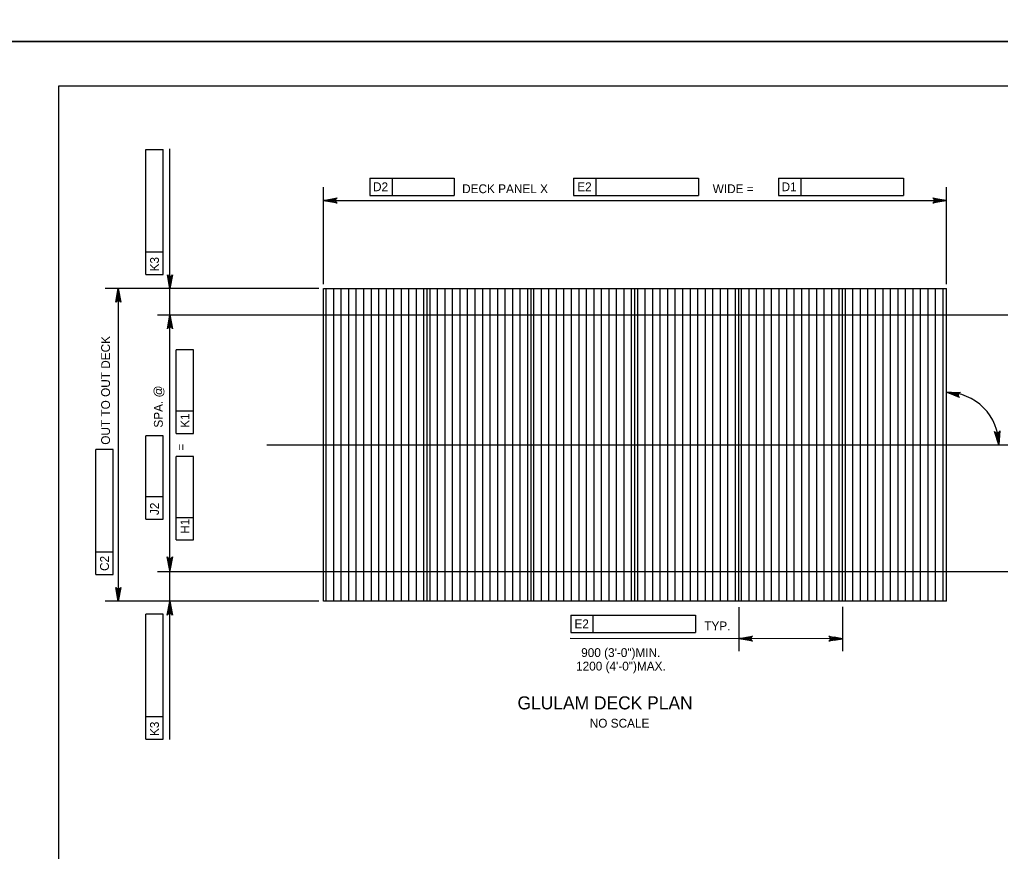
# Model space of a CAD drawing. Extents: x 638263 to 640360, y 293683 to 298655.
# Drawn here: x 639303.1 to 639636.8, y 295784 to 296067 of the extents above; entities that cross this region are included whole.
import ezdxf

# ---------------------------------------------------------------- set-up
doc = ezdxf.new("R2010")
doc.units = 0
for name, color, linetype in [('2', 7, 'Continuous'), ('4', 7, 'Continuous'), ('5', 7, 'Continuous'), ('PLT-BNDY', 7, 'Continuous')]:
    doc.layers.add(name, color=color, linetype=linetype)

msp = doc.modelspace()

# ---------------------------------------------------------------- linework, layer by layer
at = {"layer": '2'}
for p, q in [((639316.46, 295480.46), (639316.46, 296044.46)), ((639316.46, 296044.46), (640102.46, 296044.46)), ((639406.47, 295975.43), (639618.44, 295975.43)), ((639406.47, 295869.13), (639406.47, 295975.43)), ((639441.8, 295869.13), (639441.8, 295975.43)), ((639477.13, 295869.13), (639477.13, 295975.43)), ((639512.46, 295869.13), (639512.46, 295975.43)), ((639547.78, 295869.13), (639547.78, 295975.43)), ((639583.11, 295869.13), (639583.11, 295975.43)), ((639618.44, 295869.13), (639618.44, 295975.43)), ((639618.44, 295869.13), (639406.47, 295869.13))]:
    msp.add_line(p, q, dxfattribs=at)
at = {"layer": '4'}
for p, q in [((639346.04, 295980.26), (639346.04, 296022.78)), ((639346.04, 296022.78), (639351.95, 296022.78)), ((639351.95, 295980.26), (639351.95, 296022.78)), ((639354.25, 295822.05), (639354.25, 296023.02)), ((639422.27, 296013.03), (639450.94, 296013.03)), ((639422.27, 296013.03), (639422.27, 296007.12)), ((639429.83, 296013.03), (639429.83, 296007.12)), ((639450.94, 296013.03), (639450.94, 296007.12)), ((639491.54, 296013.03), (639534.06, 296013.03)), ((639491.54, 296013.03), (639491.54, 296007.12)), ((639499.1, 296013.03), (639499.1, 296007.12)), ((639534.06, 296013.03), (639534.06, 296007.12)), ((639561.33, 296013.03), (639603.85, 296013.03)), ((639561.33, 296013.03), (639561.33, 296007.12)), ((639568.89, 296013.03), (639568.89, 296007.12)), ((639603.85, 296013.03), (639603.85, 296007.12)), ((639406.47, 295976.99), (639406.47, 296009.91)), ((639422.27, 296007.12), (639450.94, 296007.12)), ((639491.54, 296007.12), (639534.06, 296007.12)), ((639561.33, 296007.12), (639603.85, 296007.12)), ((639618.44, 295976.99), (639618.44, 296009.91)), ((639406.47, 296005.41), (639618.44, 296005.41)), ((639351.95, 295987.82), (639346.04, 295987.82)), ((639346.04, 295980.26), (639351.95, 295980.26)), ((639404.91, 295975.43), (639332.16, 295975.43)), ((639336.66, 295975.43), (639336.66, 295869.13)), ((639349.96, 295966.46), (639640.33, 295966.46)), ((639356.4, 295926.16), (639356.4, 295954.56)), ((639362.31, 295954.56), (639356.4, 295954.56)), ((639362.31, 295926.15), (639362.31, 295954.56)), ((639362.31, 295933.71), (639356.4, 295933.72)), ((639346.04, 295896.98), (639346.04, 295925.39)), ((639351.95, 295925.38), (639346.04, 295925.39)), ((639351.95, 295896.98), (639351.95, 295925.38)), ((639356.4, 295926.16), (639362.31, 295926.15)), ((639329.03, 295878.19), (639329.03, 295920.71)), ((639334.93, 295920.71), (639329.03, 295920.71)), ((639334.93, 295878.18), (639334.93, 295920.71)), ((639387.19, 295922.28), (639640.33, 295922.28)), ((639356.4, 295889.93), (639356.4, 295918.33)), ((639362.31, 295918.33), (639356.4, 295918.33)), ((639362.31, 295889.92), (639362.31, 295918.33)), ((639351.95, 295904.54), (639346.04, 295904.55)), ((639346.04, 295896.98), (639351.95, 295896.98)), ((639362.31, 295897.48), (639356.4, 295897.49)), ((639356.4, 295889.93), (639362.31, 295889.92)), ((639334.93, 295885.75), (639329.03, 295885.75)), ((639329.03, 295878.19), (639334.93, 295878.18)), ((639349.96, 295879.19), (639640.33, 295879.19)), ((639404.91, 295869.13), (639332.16, 295869.13)), ((639547.78, 295867.06), (639547.78, 295852.08)), ((639583.11, 295867.13), (639583.1, 295852.08)), ((639346.04, 295822.18), (639346.04, 295864.7)), ((639351.95, 295864.69), (639346.04, 295864.7)), ((639351.95, 295822.17), (639351.95, 295864.69)), ((639490.59, 295864.32), (639533.11, 295864.32)), ((639490.59, 295864.32), (639490.59, 295858.42)), ((639498.15, 295864.32), (639498.15, 295858.42)), ((639533.11, 295864.32), (639533.11, 295858.42)), ((639490.59, 295858.42), (639533.11, 295858.42)), ((639583.11, 295856.33), (639490.4, 295856.35)), ((639351.95, 295829.73), (639346.04, 295829.74)), ((639346.04, 295822.18), (639351.95, 295822.17))]:
    msp.add_line(p, q, dxfattribs=at)
for points in [[(639406.47, 296005.41), (639411.13, 296006.28), (639410.77, 296006.03), (639410.59, 296005.72), (639410.53, 296005.41), (639410.59, 296005.09), (639410.77, 296004.78), (639411.13, 296004.53), (639406.47, 296005.41), (639410.77, 296004.78), (639410.59, 296005.09), (639406.47, 296005.41), (639410.53, 296005.41), (639410.59, 296005.72), (639406.47, 296005.41), (639410.77, 296006.03)], [(639618.44, 296005.41), (639613.78, 296004.53), (639614.14, 296004.78), (639614.32, 296005.09), (639614.38, 296005.41), (639614.32, 296005.72), (639614.14, 296006.03), (639613.78, 296006.28), (639618.44, 296005.41), (639614.14, 296006.03), (639614.32, 296005.72), (639618.44, 296005.41), (639614.38, 296005.41), (639614.32, 296005.09), (639618.44, 296005.41), (639614.14, 296004.78)], [(639354.25, 295975.43), (639353.38, 295980.09), (639353.62, 295979.73), (639353.94, 295979.54), (639354.25, 295979.49), (639354.56, 295979.54), (639354.87, 295979.73), (639355.12, 295980.09), (639354.25, 295975.43), (639354.87, 295979.73), (639354.56, 295979.54), (639354.25, 295975.43), (639354.25, 295979.49), (639353.94, 295979.54), (639354.25, 295975.43), (639353.62, 295979.73)], [(639336.66, 295975.43), (639337.54, 295970.77), (639337.29, 295971.12), (639336.98, 295971.31), (639336.66, 295971.36), (639336.35, 295971.31), (639336.04, 295971.12), (639335.79, 295970.77), (639336.66, 295975.43), (639336.04, 295971.12), (639336.35, 295971.31), (639336.66, 295975.43), (639336.66, 295971.36), (639336.98, 295971.31), (639336.66, 295975.43), (639337.29, 295971.12)], [(639354.25, 295966.46), (639355.12, 295961.8), (639354.87, 295962.16), (639354.56, 295962.34), (639354.25, 295962.4), (639353.94, 295962.34), (639353.62, 295962.16), (639353.38, 295961.8), (639354.25, 295966.46), (639353.62, 295962.16), (639353.94, 295962.34), (639354.25, 295966.46), (639354.25, 295962.4), (639354.56, 295962.34), (639354.25, 295966.46), (639354.87, 295962.16)], [(639618.45, 295940.18), (639623.19, 295940.14), (639622.79, 295939.96), (639622.54, 295939.69), (639622.43, 295939.4), (639622.42, 295939.08), (639622.55, 295938.74), (639622.85, 295938.42), (639618.45, 295940.18), (639622.55, 295938.74), (639622.42, 295939.08), (639618.45, 295940.18), (639622.43, 295939.4), (639622.54, 295939.69), (639618.45, 295940.18), (639622.79, 295939.96)], [(639636.29, 295922.28), (639634.83, 295926.79), (639635.13, 295926.47), (639635.46, 295926.32), (639635.78, 295926.31), (639636.08, 295926.4), (639636.36, 295926.62), (639636.56, 295927.01), (639636.29, 295922.28), (639636.36, 295926.62), (639636.08, 295926.4), (639636.29, 295922.28), (639635.78, 295926.31), (639635.46, 295926.32), (639636.29, 295922.28), (639635.13, 295926.47)], [(639354.2, 295879.48), (639353.33, 295884.14), (639353.58, 295883.78), (639353.89, 295883.59), (639354.2, 295883.54), (639354.51, 295883.59), (639354.83, 295883.78), (639355.07, 295884.14), (639354.2, 295879.48), (639354.83, 295883.78), (639354.51, 295883.59), (639354.2, 295879.48), (639354.2, 295883.54), (639353.89, 295883.59), (639354.2, 295879.48), (639353.58, 295883.78)], [(639336.66, 295869.13), (639335.79, 295873.79), (639336.04, 295873.43), (639336.35, 295873.25), (639336.66, 295873.19), (639336.98, 295873.25), (639337.29, 295873.43), (639337.54, 295873.79), (639336.66, 295869.13), (639337.29, 295873.43), (639336.98, 295873.25), (639336.66, 295869.13), (639336.66, 295873.19), (639336.35, 295873.25), (639336.66, 295869.13), (639336.04, 295873.43)], [(639354.23, 295869), (639355.1, 295864.34), (639354.85, 295864.7), (639354.54, 295864.88), (639354.23, 295864.93), (639353.92, 295864.88), (639353.6, 295864.7), (639353.35, 295864.34), (639354.23, 295869), (639353.6, 295864.7), (639353.92, 295864.88), (639354.23, 295869), (639354.23, 295864.93), (639354.54, 295864.88), (639354.23, 295869), (639354.85, 295864.7)], [(639547.78, 295856.34), (639552.44, 295857.21), (639552.08, 295856.96), (639551.9, 295856.65), (639551.84, 295856.34), (639551.9, 295856.02), (639552.08, 295855.71), (639552.44, 295855.46), (639547.78, 295856.34), (639552.08, 295855.71), (639551.9, 295856.02), (639547.78, 295856.34), (639551.84, 295856.34), (639551.9, 295856.65), (639547.78, 295856.34), (639552.08, 295856.96)], [(639583.11, 295856.33), (639578.45, 295855.46), (639578.81, 295855.7), (639578.99, 295856.02), (639579.04, 295856.33), (639578.99, 295856.64), (639578.81, 295856.95), (639578.45, 295857.2), (639583.11, 295856.33), (639578.81, 295856.95), (639578.99, 295856.64), (639583.11, 295856.33), (639579.04, 295856.33), (639578.99, 295856.02), (639583.11, 295856.33), (639578.81, 295855.7)]]:
    msp.add_lwpolyline(points, dxfattribs=at)
for points in [[(639409.47, 296005.91), (639409.47, 296004.91), (639406.47, 296005.41)], [(639615.44, 296005.91), (639615.44, 296004.91), (639618.44, 296005.41)], [(639354.74, 295978.38), (639353.76, 295978.38), (639354.25, 295975.43)], [(639336.16, 295972.43), (639337.16, 295972.43), (639336.66, 295975.43)], [(639354.74, 295963.51), (639353.76, 295963.51), (639354.25, 295966.46)], [(639354.74, 295882.14), (639353.76, 295882.14), (639354.25, 295879.19)], [(639336.16, 295872.13), (639337.16, 295872.13), (639336.66, 295869.13)], [(639354.74, 295866.18), (639353.76, 295866.18), (639354.25, 295869.13)], [(639550.62, 295856.81), (639550.62, 295855.86), (639547.78, 295856.34)], [(639580.27, 295856.8), (639580.27, 295855.86), (639583.11, 295856.33)]]:
    msp.add_lwpolyline(points, close=True, dxfattribs=at)
msp.add_arc((639618.44, 295922.28), 17.85, 0.0023, 90.0027, dxfattribs=at)
at = {"layer": '5'}
for p, q in [((639407.43, 295869.13), (639407.43, 295975.43)), ((639409.99, 295869.13), (639409.99, 295975.43)), ((639412.54, 295869.13), (639412.54, 295975.43)), ((639415.1, 295869.13), (639415.1, 295975.43)), ((639417.66, 295869.13), (639417.66, 295975.43)), ((639420.21, 295869.13), (639420.21, 295975.43)), ((639422.77, 295869.13), (639422.77, 295975.43)), ((639425.33, 295869.13), (639425.33, 295975.43)), ((639427.89, 295869.13), (639427.89, 295975.43)), ((639430.44, 295869.13), (639430.44, 295975.43)), ((639433, 295869.13), (639433, 295975.43)), ((639435.56, 295869.13), (639435.56, 295975.43)), ((639438.11, 295869.13), (639438.11, 295975.43)), ((639440.67, 295869.13), (639440.67, 295975.43)), ((639442.76, 295869.13), (639442.76, 295975.43)), ((639445.31, 295869.13), (639445.31, 295975.43)), ((639447.87, 295869.13), (639447.87, 295975.43)), ((639450.43, 295869.13), (639450.43, 295975.43)), ((639452.99, 295869.13), (639452.99, 295975.43)), ((639455.54, 295869.13), (639455.54, 295975.43)), ((639458.1, 295869.13), (639458.1, 295975.43)), ((639460.66, 295869.13), (639460.66, 295975.43)), ((639463.21, 295869.13), (639463.21, 295975.43)), ((639465.77, 295869.13), (639465.77, 295975.43)), ((639468.33, 295869.13), (639468.33, 295975.43)), ((639470.89, 295869.13), (639470.89, 295975.43)), ((639473.44, 295869.13), (639473.44, 295975.43)), ((639476, 295869.13), (639476, 295975.43)), ((639478.09, 295869.13), (639478.09, 295975.43)), ((639480.64, 295869.13), (639480.64, 295975.43)), ((639483.2, 295869.13), (639483.2, 295975.43)), ((639485.76, 295869.13), (639485.76, 295975.43)), ((639488.31, 295869.13), (639488.31, 295975.43)), ((639490.87, 295869.13), (639490.87, 295975.43)), ((639493.43, 295869.13), (639493.43, 295975.43)), ((639495.99, 295869.13), (639495.99, 295975.43)), ((639498.54, 295869.13), (639498.54, 295975.43)), ((639501.1, 295869.13), (639501.1, 295975.43)), ((639503.66, 295869.13), (639503.66, 295975.43)), ((639506.21, 295869.13), (639506.21, 295975.43)), ((639508.77, 295869.13), (639508.77, 295975.43)), ((639511.33, 295869.13), (639511.33, 295975.43)), ((639513.41, 295869.13), (639513.41, 295975.43)), ((639515.97, 295869.13), (639515.97, 295975.43)), ((639518.53, 295869.13), (639518.53, 295975.43)), ((639521.09, 295869.13), (639521.09, 295975.43)), ((639523.64, 295869.13), (639523.64, 295975.43)), ((639526.2, 295869.13), (639526.2, 295975.43)), ((639528.76, 295869.13), (639528.76, 295975.43)), ((639531.31, 295869.13), (639531.31, 295975.43)), ((639533.87, 295869.13), (639533.87, 295975.43)), ((639536.43, 295869.13), (639536.43, 295975.43)), ((639538.99, 295869.13), (639538.99, 295975.43)), ((639541.54, 295869.13), (639541.54, 295975.43)), ((639544.1, 295869.13), (639544.1, 295975.43)), ((639546.66, 295869.13), (639546.66, 295975.43)), ((639548.74, 295869.13), (639548.74, 295975.43)), ((639551.3, 295869.13), (639551.3, 295975.43)), ((639553.86, 295869.13), (639553.86, 295975.43)), ((639556.41, 295869.13), (639556.41, 295975.43)), ((639558.97, 295869.13), (639558.97, 295975.43)), ((639561.53, 295869.13), (639561.53, 295975.43)), ((639564.09, 295869.13), (639564.09, 295975.43)), ((639566.64, 295869.13), (639566.64, 295975.43)), ((639569.2, 295869.13), (639569.2, 295975.43)), ((639571.76, 295869.13), (639571.76, 295975.43)), ((639574.31, 295869.13), (639574.31, 295975.43)), ((639576.87, 295869.13), (639576.87, 295975.43)), ((639579.43, 295869.13), (639579.43, 295975.43)), ((639581.99, 295869.13), (639581.99, 295975.43)), ((639584.07, 295869.13), (639584.07, 295975.43)), ((639586.63, 295869.13), (639586.63, 295975.43)), ((639589.18, 295869.13), (639589.18, 295975.43)), ((639591.74, 295869.13), (639591.74, 295975.43)), ((639594.3, 295869.13), (639594.3, 295975.43)), ((639596.86, 295869.13), (639596.86, 295975.43)), ((639599.41, 295869.13), (639599.41, 295975.43)), ((639601.97, 295869.13), (639601.97, 295975.43)), ((639604.53, 295869.13), (639604.53, 295975.43)), ((639607.09, 295869.13), (639607.09, 295975.43)), ((639609.64, 295869.13), (639609.64, 295975.43)), ((639612.2, 295869.13), (639612.2, 295975.43)), ((639614.76, 295869.13), (639614.76, 295975.43)), ((639617.31, 295869.13), (639617.31, 295975.43))]:
    msp.add_line(p, q, dxfattribs=at)
at = {"layer": 'PLT-BNDY'}
for points in [[(639276.46, 296653.46), (640117.46, 296653.46), (640117.46, 296059.46), (639276.46, 296059.46)], [(639276.46, 296059.46), (640117.46, 296059.46), (640117.46, 295465.46), (639276.46, 295465.46)]]:
    msp.add_lwpolyline(points, close=True, dxfattribs=at)

# ---------------------------------------------------------------- texts
at = {"layer": '4'}
for s, rotation, p in [('D2', 359.9382, (639423.35, 296008.58)), ('E2', 359.9382, (639492.83, 296008.58)), ('D1', 359.9382, (639562.35, 296008.58)), ('K3', 89.9382, (639350.49, 295981.29)), ('OUT TO OUT DECK', 90, (639333.85, 295922.31)), ('SPA. @', 90, (639351.8, 295928.13)), ('K1', 89.9382, (639360.85, 295928.09)), ('=', 90, (639359.53, 295920.36)), ('J2', 89.9382, (639350.49, 295898.38)), ('H1', 89.9382, (639360.85, 295892.01)), ('C2', 89.9382, (639333.48, 295879.37)), ('E2', 359.9382, (639491.88, 295859.87)), ('TYP.', 359.9382, (639536.04, 295859.18)), ('K3', 89.9382, (639350.49, 295823.2))]:
    msp.add_text(s, height=3, rotation=rotation, dxfattribs=at).set_placement(p)
for s, height, p in [('DECK PANEL X', 3, (639453.66, 296007.91)), ('WIDE =', 3, (639538.92, 296007.91)), ('900 (3\'-0")MIN.', 3, (639494.17, 295850.09)), ('1200 (4\'-0")MAX.', 3, (639492.43, 295845.49)), ('GLULAM DECK PLAN', 4.4292, (639472.51, 295832.27)), ('NO SCALE', 3, (639497.08, 295826.06))]:
    msp.add_text(s, height=height, dxfattribs=at).set_placement(p)

doc.saveas('drawing.dxf')
